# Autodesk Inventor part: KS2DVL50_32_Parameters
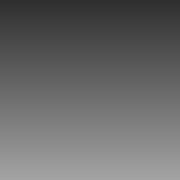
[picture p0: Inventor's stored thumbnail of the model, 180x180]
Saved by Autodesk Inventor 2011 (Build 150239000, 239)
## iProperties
Created: 2010-11
Document SubType Name: Modeling
Designer: TB
Density: 1 g/cm^3
Slaglengde: 100,000 mm
Vinkel_Minusport: 0.00 deg
Forlengelse_rør: 0.000 mm
Minusport2: 180.00 deg
Author: TB
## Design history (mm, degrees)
other parameters: "Slaglengde" = 100 [user parameter], "Forlengelse_rør" = 0 [user parameter], "Vinkel_Minusport" = 0 deg [user parameter], "Minusport2" = 180 deg [user parameter]
